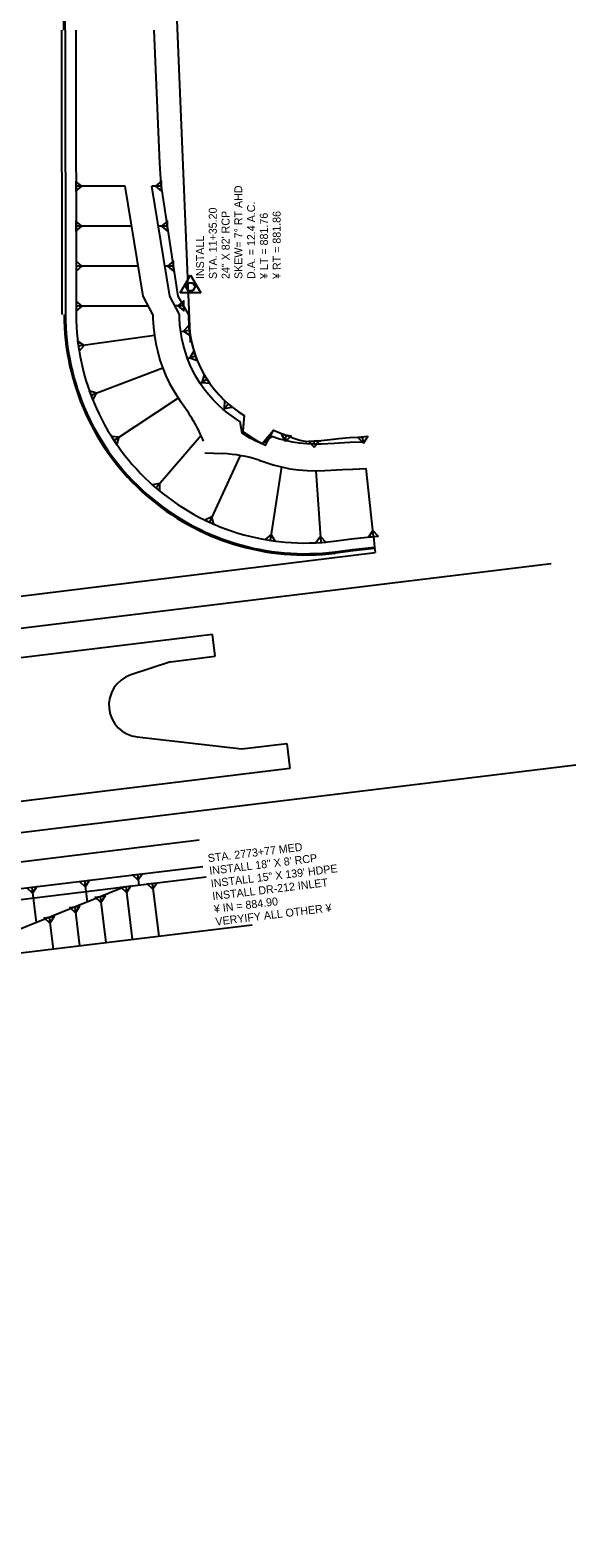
# Model space of a CAD drawing. Extents: x 18436148 to 18440034, y 7649939 to 7652226.
# Drawn here: x 18438335 to 18438540, y 7649939 to 7650505 of the extents above; entities that cross this region are included whole.
import ezdxf

# ---------------------------------------------------------------- set-up
doc = ezdxf.new("R2010")
doc.units = 0
for name, color, linetype in [('ATVEHICLE', 7, 'Continuous'), ('Default', 7, 'Continuous'), ('dsnCellsScaleBlock', 7, 'Continuous'), ('ROWTitleBlock', 7, 'Continuous'), ('Seeding', 7, 'Continuous'), ('TC_PCCPavement', 7, 'Continuous'), ('TC_Subbase', 7, 'Continuous'), ('TL_ShoulderBtm', 7, 'Continuous'), ('TSDETAILS', 7, 'Continuous'), ('TSOUTLINE', 7, 'Continuous')]:
    doc.layers.add(name, color=color, linetype=linetype)

msp = doc.modelspace()

# ---------------------------------------------------------------- linework, layer by layer
at = {"layer": 'ATVEHICLE'}
for p, q in [((18438348.05, 7650505.07), (18438348.2, 7650398.25)), ((18438157.51, 7650270.99), (18438464.57, 7650308.82)), ((18438464.33, 7650310.8), (18438464.57, 7650308.82)), ((18438403.52, 7650277.97), (18438255.05, 7650259.88)), ((18438404.5, 7650269.92), (18438403.52, 7650277.97)), ((18438387.63, 7650267.79), (18438372.73, 7650262.8)), ((18438387.63, 7650267.79), (18438404.5, 7650269.92)), ((18438375.2, 7650239.5), (18438414.48, 7650235.07)), ((18438414.48, 7650235.07), (18438431.36, 7650237.03)), ((18438431.36, 7650237.03), (18438432.51, 7650227.61)), ((18438432.51, 7650227.61), (18437563.42, 7650121.72))]:
    msp.add_line(p, q, dxfattribs=at)
msp.add_lwpolyline([(18438449.57, 7650309.09), (18438456.22, 7650309.94), (18438464.33, 7650310.8)], dxfattribs=at)
for centre, radius, start, end in [((18431834.06, 7650496.24), 6514, 0.077652, 3.256258), ((18438438.2, 7650398.37), 90, 180.0777, 277.2885), ((18438376.54, 7650251.42), 12, 108.511, 263.5698)]:
    msp.add_arc(centre, radius, start, end, dxfattribs=at)
at = {"layer": 'Default'}
for p, q in [((18438062.74, 7650159.8), (18438398.49, 7650200.8)), ((18438063.95, 7650149.87), (18438399.87, 7650190.89)), ((18438064.43, 7650145.9), (18438401.05, 7650187))]:
    msp.add_line(p, q, dxfattribs=at)
at = {"layer": 'Seeding'}
for p, q in [((18438391.31, 7650406.35), (18438395.18, 7650413.07)), ((18438393.43, 7650408.59), (18438394.31, 7650410.11)), ((18438394.31, 7650410.11), (18438396.06, 7650410.11)), ((18438395.18, 7650413.07), (18438399.06, 7650406.35)), ((18438396.06, 7650410.11), (18438396.93, 7650408.59)), ((18438399.06, 7650406.35), (18438391.31, 7650406.35)), ((18438394.31, 7650407.08), (18438393.43, 7650408.59)), ((18438396.06, 7650407.08), (18438394.31, 7650407.08)), ((18438396.93, 7650408.59), (18438396.06, 7650407.08))]:
    msp.add_line(p, q, dxfattribs=at)
at = {"layer": 'TC_PCCPavement'}
msp.add_line((18438386.14, 7650605.99), (18438395.03, 7650387.67), dxfattribs=at)
at = {"layer": 'TC_Subbase'}
for p, q in [((18438370.64, 7650446.42), (18438352.13, 7650446.4)), ((18438384.23, 7650446.44), (18438380.68, 7650446.43)), ((18438373.11, 7650431.42), (18438352.15, 7650431.4)), ((18438386.59, 7650431.44), (18438383.13, 7650431.44)), ((18438375.58, 7650416.43), (18438352.17, 7650416.4)), ((18438388.85, 7650416.45), (18438385.59, 7650416.44)), ((18438379.4, 7650401.43), (18438352.19, 7650401.4)), ((18438392.68, 7650401.45), (18438389.4, 7650401.45)), ((18438394.81, 7650392.24), (18438391.53, 7650391.77)), ((18438381.62, 7650390.37), (18438353.04, 7650386.33)), ((18438394.12, 7650381.65), (18438397.06, 7650382.76)), ((18438384.77, 7650378.1), (18438357.79, 7650367.86)), ((18438398.89, 7650372.34), (18438401.38, 7650373.99)), ((18438390.6, 7650366.85), (18438366.49, 7650350.89)), ((18438407.57, 7650362.6), (18438409.35, 7650364.69)), ((18438399.15, 7650352.77), (18438382.26, 7650333.05)), ((18438430.9, 7650350.95), (18438431.2, 7650352.86)), ((18438460.12, 7650350.28), (18438459.92, 7650352.17)), ((18438441.52, 7650350.63), (18438441.61, 7650349.42)), ((18438400.62, 7650346.22), (18438407.38, 7650345.95)), ((18438413.82, 7650345.27), (18438402.31, 7650320.21)), ((18438429.37, 7650340.95), (18438425.12, 7650313.37)), ((18438442.3, 7650339.52), (18438444.18, 7650312.58)), ((18438463.91, 7650314.78), (18438461.18, 7650340.35)), ((18438375.24, 7650187.88), (18438375.73, 7650183.91)), ((18438298.74, 7650154.36), (18438370.48, 7650183.27)), ((18438335.54, 7650183.03), (18438337.15, 7650169.84)), ((18438355.39, 7650185.46), (18438356.35, 7650177.58)), ((18438370.9, 7650183.32), (18438373.32, 7650163.47)), ((18438380.82, 7650184.53), (18438383.25, 7650164.68)), ((18438361.28, 7650179.56), (18438363.39, 7650162.26)), ((18438342.08, 7650171.83), (18438343.54, 7650159.83)), ((18438351.68, 7650175.69), (18438353.47, 7650161.05)), ((18438324.19, 7650157.47), (18438418.38, 7650168.97))]:
    msp.add_line(p, q, dxfattribs=at)
for points in [[(18438354.38, 7650446.4), (18438352.13, 7650448.27), (18438352.13, 7650444.52)], [(18438382.08, 7650446.44), (18438384.34, 7650444.56), (18438384.33, 7650448.31)], [(18438354.4, 7650431.4), (18438352.15, 7650433.27), (18438352.15, 7650429.52)], [(18438384.34, 7650431.44), (18438386.59, 7650429.57), (18438386.59, 7650433.32)], [(18438354.42, 7650416.4), (18438352.17, 7650418.27), (18438352.18, 7650414.52)], [(18438386.6, 7650416.44), (18438388.85, 7650414.57), (18438388.85, 7650418.32)], [(18438354.44, 7650401.4), (18438352.19, 7650403.27), (18438352.2, 7650399.52)], [(18438390.43, 7650401.45), (18438392.68, 7650399.58), (18438392.68, 7650403.33)], [(18438392.58, 7650391.92), (18438395.07, 7650390.38), (18438394.55, 7650394.09)], [(18438355.27, 7650386.65), (18438352.78, 7650388.19), (18438353.31, 7650384.48)], [(18438394.96, 7650381.96), (18438397.72, 7650381.01), (18438396.39, 7650384.51)], [(18438399.5, 7650372.75), (18438402.42, 7650372.43), (18438400.35, 7650375.56)], [(18438359.89, 7650368.66), (18438357.12, 7650369.62), (18438358.45, 7650366.11)], [(18438407.89, 7650362.98), (18438410.78, 7650363.47), (18438407.93, 7650365.9)], [(18438368.37, 7650352.13), (18438365.46, 7650352.45), (18438367.53, 7650349.33)], [(18438430.85, 7650350.63), (18438433.05, 7650352.57), (18438429.34, 7650353.14)], [(18438460.16, 7650349.93), (18438461.79, 7650352.37), (18438458.06, 7650351.97)], [(18438441.68, 7650348.39), (18438443.4, 7650350.76), (18438439.65, 7650350.5)], [(18438383.72, 7650334.76), (18438380.83, 7650334.27), (18438383.68, 7650331.83)], [(18438403.25, 7650322.26), (18438400.61, 7650320.99), (18438404.02, 7650319.43)], [(18438425.46, 7650315.59), (18438423.27, 7650313.65), (18438426.98, 7650313.08)], [(18438444.02, 7650314.82), (18438442.31, 7650312.45), (18438446.05, 7650312.71)], [(18438463.67, 7650317.02), (18438462.04, 7650314.58), (18438465.77, 7650314.98)], [(18438375.51, 7650185.65), (18438373.38, 7650187.66), (18438377.1, 7650188.11)], [(18438335.81, 7650180.8), (18438333.68, 7650182.81), (18438337.4, 7650183.26)], [(18438355.66, 7650183.23), (18438353.53, 7650185.23), (18438357.25, 7650185.69)], [(18438371.17, 7650181.09), (18438369.03, 7650183.1), (18438372.76, 7650183.55)], [(18438381.09, 7650182.3), (18438378.96, 7650184.31), (18438382.68, 7650184.76)], [(18438361.55, 7650177.33), (18438359.42, 7650179.34), (18438363.14, 7650179.79)], [(18438342.35, 7650169.59), (18438340.22, 7650171.6), (18438343.94, 7650172.05)], [(18438351.95, 7650173.46), (18438349.82, 7650175.47), (18438353.54, 7650175.92)]]:
    msp.add_lwpolyline(points, close=True, dxfattribs=at)
for points in [[(18438381.07, 7650398.29), (18438377.44, 7650405.11), (18438370.64, 7650446.42)], [(18438391.07, 7650398.3), (18438387.44, 7650405.13), (18438380.68, 7650446.43)], [(18438381.07, 7650398.29), (18438381.09, 7650396.7), (18438381.27, 7650393.53), (18438381.62, 7650390.37), (18438382.15, 7650387.24), (18438382.86, 7650384.15), (18438383.73, 7650381.1), (18438384.77, 7650378.1), (18438385.98, 7650375.16), (18438387.35, 7650372.3), (18438388.87, 7650369.52), (18438391.46, 7650365.52)], [(18438416.97, 7650352.14), (18438414.55, 7650353.61), (18438413.89, 7650357.96), (18438411.69, 7650359.37), (18438409.56, 7650360.91), (18438407.53, 7650362.56), (18438405.59, 7650364.31), (18438403.75, 7650366.18), (18438402.01, 7650368.14), (18438400.39, 7650370.2), (18438398.89, 7650372.34), (18438397.5, 7650374.57), (18438396.25, 7650376.86), (18438395.12, 7650379.23), (18438394.12, 7650381.65), (18438393.26, 7650384.12), (18438392.54, 7650386.64), (18438391.96, 7650389.19), (18438391.53, 7650391.77), (18438391.23, 7650394.37), (18438391.09, 7650396.99), (18438391.07, 7650398.3)], [(18438394.5, 7650398.31), (18438394.49, 7650397.09), (18438394.58, 7650394.66), (18438394.81, 7650392.24), (18438395.17, 7650389.83), (18438395.67, 7650387.44), (18438396.3, 7650385.08), (18438397.06, 7650382.76), (18438397.96, 7650380.49), (18438398.98, 7650378.26), (18438400.12, 7650376.1), (18438401.39, 7650374), (18438402.76, 7650371.96), (18438404.25, 7650370.01), (18438405.85, 7650368.14), (18438407.55, 7650366.36), (18438409.35, 7650364.69), (18438411.25, 7650363.11), (18438413.23, 7650361.65), (18438415.3, 7650360.3), (18438414.9, 7650354.26), (18438417.2, 7650352.63), (18438417.21, 7650352.63)], [(18438460.12, 7650350.28), (18438455.11, 7650350.12), (18438451.1, 7650349.9), (18438449.26, 7650349.81), (18438444.44, 7650349.56), (18438444.34, 7650349.55), (18438441.6, 7650349.5), (18438438.88, 7650349.6), (18438436.18, 7650349.85), (18438433.51, 7650350.27), (18438430.89, 7650350.84), (18438428.31, 7650351.56), (18438425.79, 7650352.43), (18438422.08, 7650349.62), (18438419.49, 7650350.81), (18438416.97, 7650352.14)], [(18438417.2, 7650352.63), (18438419.61, 7650351.14), (18438422.13, 7650349.78), (18438426.42, 7650354.75), (18438428.77, 7650353.73), (18438431.2, 7650352.86), (18438433.67, 7650351.92), (18438436.23, 7650351.08), (18438438.87, 7650350.58), (18438441.52, 7650350.63), (18438444.18, 7650350.83), (18438444.28, 7650350.84), (18438449.05, 7650351.45), (18438450.88, 7650351.68), (18438454.91, 7650352.04), (18438459.92, 7650352.17)], [(18438420.97, 7650343.5), (18438426.24, 7650341.77), (18438429.36, 7650340.95), (18438432.54, 7650340.31), (18438435.77, 7650339.86), (18438439.02, 7650339.6), (18438442.3, 7650339.52), (18438445.71, 7650339.64), (18438452.37, 7650339.98), (18438456.17, 7650340.18), (18438461.18, 7650340.35)]]:
    msp.add_lwpolyline(points, dxfattribs=at)
for centre, radius, start, end in [((18438337.98, 7650324.57), 67.36, 22.82, 37.4461), ((18438405.39, 7650295.99), 50, 71.8527, 87.7262)]:
    msp.add_arc(centre, radius, start, end, dxfattribs=at)
at = {"layer": 'TL_ShoulderBtm'}
for p, q in [((18438346.72, 7650505.07), (18438346.86, 7650398.25)), ((18438530.78, 7650304.56), (18436148.4, 7650014.28)), ((18438540.01, 7650228.87), (18436157.63, 7649938.59))]:
    msp.add_line(p, q, dxfattribs=at)
msp.add_lwpolyline([(18438464.38, 7650310.31), (18438456.27, 7650309.44), (18438449.64, 7650308.59)], dxfattribs=at)
for centre, radius, start, end in [((18431834.06, 7650496.24), 6513.5, 0.077652, 3.256258), ((18438438.2, 7650398.37), 90.5, 180.0779, 277.2848)]:
    msp.add_arc(centre, radius, start, end, dxfattribs=at)
at = {"layer": 'TSDETAILS'}
for p, q in [((18438352.05, 7650505.08), (18438352.2, 7650398.25)), ((18438463.91, 7650314.78), (18438464.33, 7650310.8))]:
    msp.add_line(p, q, dxfattribs=at)
msp.add_lwpolyline([(18438449.11, 7650313.06), (18438455.75, 7650313.91), (18438463.91, 7650314.78)], dxfattribs=at)
msp.add_arc((18438438.2, 7650398.37), 86, 180.0777, 277.2885, dxfattribs=at)
at = {"layer": 'TSOUTLINE'}
for points in [[(18438394.5, 7650398.31), (18438390.55, 7650405.13), (18438384.23, 7650447.12), (18438383.65, 7650455.12), (18438381.54, 7650505.12)], [(18438394.5, 7650398.31), (18438394.58, 7650394.66), (18438394.8, 7650392.32), (18438395.17, 7650389.83), (18438395.98, 7650386.26), (18438397.06, 7650382.76), (18438397.96, 7650380.49), (18438398.98, 7650378.26), (18438400.12, 7650376.1), (18438401.39, 7650374), (18438402.76, 7650371.96), (18438404.25, 7650370.01), (18438405.85, 7650368.14), (18438406.7, 7650367.25), (18438407.55, 7650366.36), (18438409.35, 7650364.69), (18438411.25, 7650363.11), (18438413.23, 7650361.65), (18438415.3, 7650360.3), (18438414.68, 7650353.84), (18438416.99, 7650352.18), (18438423.41, 7650349.15), (18438426.42, 7650354.75), (18438428.77, 7650353.73), (18438431.2, 7650352.86), (18438433.67, 7650351.92), (18438436.23, 7650351.08), (18438438.87, 7650350.58), (18438444.28, 7650350.84), (18438450.88, 7650351.68), (18438454.91, 7650352.04), (18438459.92, 7650352.17)]]:
    msp.add_lwpolyline(points, dxfattribs=at)

# ---------------------------------------------------------------- texts
at = {"layer": 'dsnCellsScaleBlock'}
for s, p in [('SKEW= 7° RT AHD', (18438414.7, 7650411.58)), ('STA. 11+35.20', (18438405.1, 7650411.56)), ('D.A. = 12.4 A.C.', (18438419.5, 7650411.58)), ('24" X 82\' RCP', (18438409.9, 7650411.57)), ('¥ LT = 881.76', (18438424.3, 7650411.59)), ('¥ RT = 881.86', (18438429.1, 7650411.6)), ('INSTALL', (18438400.3, 7650411.56))]:
    msp.add_text(s, height=3, rotation=90.0777, dxfattribs=at).set_placement(p)
at = {"layer": 'ROWTitleBlock'}
for s, p in [('STA. 2773+77 MED', (18438401.87, 7650192.45)), ('INSTALL 18" X 8\' RCP', (18438402.45, 7650187.69)), ('INSTALL 15" X 139\' HDPE', (18438403.03, 7650182.92)), ('INSTALL DR-212 INLET', (18438403.61, 7650178.16)), ('¥ IN = 884.90', (18438404.19, 7650173.39)), ('VERYIFY ALL OTHER ¥', (18438404.77, 7650168.63))]:
    msp.add_text(s, height=3, rotation=6.947, dxfattribs=at).set_placement(p)

doc.saveas('drawing.dxf')
